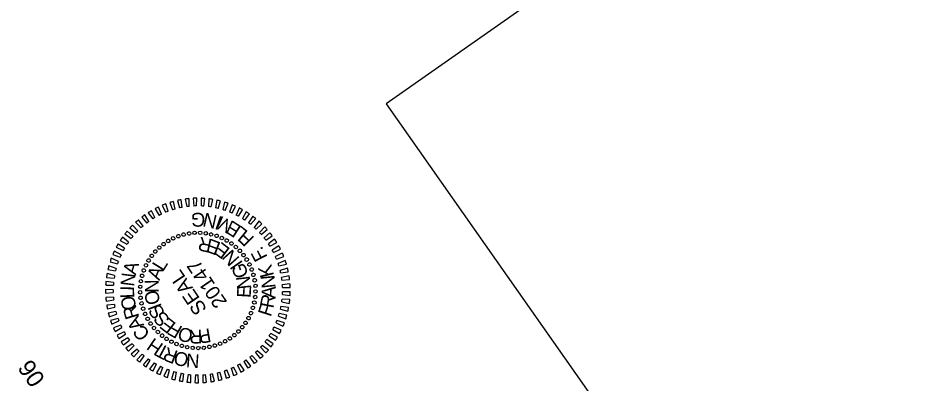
# Model space of a CAD drawing. Extents: x 2046262 to 2047823, y 758628 to 760417.
# Drawn here: x 2046261.8 to 2046652, y 759808.2 to 759966.9 of the extents above; entities that cross this region are included whole.
import ezdxf

# ---------------------------------------------------------------- set-up
doc = ezdxf.new("R2010")
doc.units = 0
for name, color, linetype in [('Sheet Clip Boundary CELL', 7, 'Continuous'), ('Sheet Data Field CELL', 7, 'Continuous'), ('Sheet PE Seal Cell', 7, 'Continuous')]:
    doc.layers.add(name, color=color, linetype=linetype)

msp = doc.modelspace()

# ---------------------------------------------------------------- linework, layer by layer
at = {"layer": 'Sheet Clip Boundary CELL'}
msp.add_lwpolyline([(2046953.28, 758800.94), (2047822.73, 759389.82), (2047107.57, 760411.26), (2046421.17, 759929.65), (2046541.36, 759758.35), (2046449.64, 759693.99), (2046540.41, 759564.59), (2046459.01, 759507.49)], close=True, dxfattribs=at)
at = {"layer": 'Sheet PE Seal Cell'}
for p, q in [((2046326.79, 759883.05), (2046325.8, 759886.25)), ((2046327.49, 759886.84), (2046328.69, 759883.7)), ((2046329.79, 759884.03), (2046329.08, 759887.31)), ((2046330.81, 759887.74), (2046331.73, 759884.52)), ((2046332.86, 759884.75), (2046332.43, 759888.08)), ((2046334.2, 759888.36), (2046334.84, 759885.07)), ((2046335.98, 759885.2), (2046335.84, 759888.55)), ((2046337.63, 759888.69), (2046337.98, 759885.35)), ((2046339.13, 759885.38), (2046339.28, 759888.74)), ((2046341.07, 759888.71), (2046341.13, 759885.36)), ((2046342.28, 759885.3), (2046342.72, 759888.62)), ((2046344.5, 759888.45), (2046344.28, 759885.1)), ((2046345.41, 759884.94), (2046346.13, 759888.21)), ((2046347.9, 759887.89), (2046347.38, 759884.57)), ((2046348.5, 759884.31), (2046349.5, 759887.51)), ((2046351.23, 759887.04), (2046350.44, 759883.78)), ((2046351.53, 759883.42), (2046352.8, 759886.53)), ((2046354.48, 759885.9), (2046353.41, 759882.72)), ((2046318.17, 759882.46), (2046320.12, 759879.73)), ((2046321.11, 759880.33), (2046319.58, 759883.32)), ((2046321.15, 759884.19), (2046322.86, 759881.3)), ((2046323.89, 759881.81), (2046322.63, 759884.92)), ((2046324.26, 759885.65), (2046325.72, 759882.63)), ((2046354.47, 759882.27), (2046356, 759885.26)), ((2046357.62, 759884.49), (2046356.28, 759881.42)), ((2046357.3, 759880.88), (2046359.08, 759883.72)), ((2046360.63, 759882.82), (2046359.03, 759879.87)), ((2046359.99, 759879.25), (2046362.01, 759881.92)), ((2046312.71, 759878.28), (2046315.1, 759875.93)), ((2046315.97, 759876.68), (2046313.95, 759879.36)), ((2046315.35, 759880.49), (2046317.53, 759877.94)), ((2046318.46, 759878.62), (2046316.68, 759881.46)), ((2046363.48, 759880.89), (2046361.63, 759878.09)), ((2046362.54, 759877.39), (2046364.78, 759879.88)), ((2046366.15, 759878.73), (2046364.07, 759876.09)), ((2046311.53, 759872.21), (2046309.09, 759874.5)), ((2046310.27, 759875.85), (2046312.86, 759873.71)), ((2046313.65, 759874.54), (2046311.41, 759877.04)), ((2046364.92, 759875.32), (2046367.37, 759877.61)), ((2046368.63, 759876.34), (2046366.33, 759873.9)), ((2046367.11, 759873.05), (2046369.75, 759875.12)), ((2046306.06, 759870.41), (2046308.98, 759868.75)), ((2046309.62, 759869.7), (2046306.98, 759871.78)), ((2046308.05, 759873.22), (2046310.81, 759871.31)), ((2046370.9, 759873.75), (2046368.4, 759871.51)), ((2046369.1, 759870.6), (2046371.9, 759872.44)), ((2046372.93, 759870.97), (2046370.25, 759868.96)), ((2046304.32, 759867.44), (2046307.37, 759866.03)), ((2046307.93, 759867.04), (2046305.13, 759868.88)), ((2046370.87, 759867.99), (2046373.82, 759869.58)), ((2046374.72, 759868.03), (2046371.87, 759866.26)), ((2046372.41, 759865.24), (2046375.49, 759866.57)), ((2046305.26, 759861.33), (2046302.19, 759862.67)), ((2046302.85, 759864.33), (2046306, 759863.19)), ((2046306.47, 759864.24), (2046303.52, 759865.84)), ((2046376.25, 759864.95), (2046373.26, 759863.42)), ((2046373.71, 759862.36), (2046376.89, 759863.43)), ((2046304.31, 759858.32), (2046301.13, 759859.39)), ((2046301.64, 759861.11), (2046304.88, 759860.24)), ((2046377.51, 759861.74), (2046374.4, 759860.48)), ((2046374.75, 759859.39), (2046378.01, 759860.17)), ((2046303.61, 759855.25), (2046300.35, 759856.04)), ((2046300.72, 759857.79), (2046304.02, 759857.21)), ((2046378.49, 759858.44), (2046375.28, 759857.45)), ((2046375.54, 759856.33), (2046378.85, 759856.83)), ((2046379.18, 759855.07), (2046375.9, 759854.36)), ((2046299.75, 759850.98), (2046303.1, 759850.98)), ((2046303.19, 759852.12), (2046299.87, 759852.63)), ((2046300.09, 759854.41), (2046303.43, 759854.11)), ((2046376.06, 759853.22), (2046379.41, 759853.44)), ((2046379.58, 759851.65), (2046376.25, 759851.23)), ((2046303.03, 759848.97), (2046299.68, 759849.19)), ((2046299.7, 759847.54), (2046303.04, 759847.82)), ((2046339.68, 759848.74), (2046339.68, 759848.74)), ((2046376.29, 759846.93), (2046379.62, 759846.56)), ((2046376.31, 759850.08), (2046379.66, 759850.01)), ((2046379.68, 759848.21), (2046376.33, 759848.08)), ((2046303.15, 759845.82), (2046299.79, 759845.75)), ((2046299.95, 759844.11), (2046303.26, 759844.68)), ((2046376, 759843.79), (2046379.29, 759843.14)), ((2046379.49, 759844.78), (2046376.13, 759844.93)), ((2046303.53, 759842.69), (2046300.2, 759842.33)), ((2046300.5, 759840.71), (2046303.74, 759841.56)), ((2046304.19, 759839.61), (2046300.89, 759838.96)), ((2046375.44, 759840.68), (2046378.66, 759839.75)), ((2046379, 759841.37), (2046375.67, 759841.81)), ((2046301.33, 759837.37), (2046304.49, 759838.5)), ((2046305.1, 759836.59), (2046301.88, 759835.67)), ((2046302.45, 759834.12), (2046305.5, 759835.51)), ((2046377.15, 759834.74), (2046373.95, 759835.75)), ((2046374.61, 759837.64), (2046377.74, 759836.44)), ((2046378.22, 759838.02), (2046374.94, 759838.74)), ((2046306.28, 759833.66), (2046303.14, 759832.46)), ((2046303.84, 759830.97), (2046306.77, 759832.62)), ((2046372.19, 759831.82), (2046375.07, 759830.1)), ((2046375.81, 759831.57), (2046372.71, 759832.85)), ((2046373.53, 759834.68), (2046376.55, 759833.21)), ((2046307.7, 759830.85), (2046304.68, 759829.38)), ((2046305.5, 759827.96), (2046308.27, 759829.85)), ((2046309.35, 759828.16), (2046306.47, 759826.45)), ((2046372.34, 759825.64), (2046369.5, 759827.43)), ((2046370.62, 759829.09), (2046373.34, 759827.13)), ((2046374.2, 759828.53), (2046371.22, 759830.07)), ((2046307.42, 759825.1), (2046310.01, 759827.22)), ((2046311.23, 759825.63), (2046308.51, 759823.67)), ((2046309.57, 759822.41), (2046311.97, 759824.75)), ((2046366.8, 759824.08), (2046369.14, 759821.68)), ((2046370.23, 759822.92), (2046367.56, 759824.94)), ((2046368.82, 759826.5), (2046371.36, 759824.31)), ((2046313.33, 759823.27), (2046310.78, 759821.09)), ((2046311.94, 759819.92), (2046314.14, 759822.46)), ((2046315.61, 759821.1), (2046313.26, 759818.7)), ((2046314.52, 759817.64), (2046316.49, 759820.36)), ((2046362.17, 759819.8), (2046364.07, 759817.03)), ((2046365.36, 759818.07), (2046363.07, 759820.52)), ((2046364.58, 759821.84), (2046366.71, 759819.25)), ((2046367.9, 759820.39), (2046365.41, 759822.63)), ((2046318.08, 759819.13), (2046315.94, 759816.54)), ((2046317.29, 759815.59), (2046319.02, 759818.47)), ((2046320.7, 759817.39), (2046318.8, 759814.62)), ((2046320.22, 759813.79), (2046321.69, 759816.81)), ((2046323.47, 759815.87), (2046321.81, 759812.95)), ((2046356.88, 759816.37), (2046358.28, 759813.32)), ((2046359.72, 759814.12), (2046357.89, 759816.93)), ((2046359.6, 759817.97), (2046361.25, 759815.05)), ((2046362.63, 759815.97), (2046360.56, 759818.61)), ((2046323.3, 759812.25), (2046324.51, 759815.38)), ((2046326.35, 759814.6), (2046324.95, 759811.55)), ((2046326.5, 759810.97), (2046327.43, 759814.2)), ((2046329.34, 759813.58), (2046328.2, 759810.42)), ((2046329.79, 759809.98), (2046330.45, 759813.27)), ((2046332.4, 759812.82), (2046331.54, 759809.58)), ((2046333.16, 759809.27), (2046333.53, 759812.61)), ((2046335.51, 759812.33), (2046334.94, 759809.02)), ((2046336.58, 759808.86), (2046336.66, 759812.21)), ((2046338.66, 759812.1), (2046338.37, 759808.76)), ((2046340.02, 759808.74), (2046339.81, 759812.09)), ((2046341.81, 759812.15), (2046341.81, 759808.8)), ((2046343.45, 759808.92), (2046342.96, 759812.24)), ((2046344.95, 759812.47), (2046345.23, 759809.13)), ((2046346.86, 759809.39), (2046346.08, 759812.65)), ((2046348.05, 759813.06), (2046348.62, 759809.75)), ((2046350.22, 759810.15), (2046349.16, 759813.34)), ((2046351.08, 759813.91), (2046351.94, 759810.66)), ((2046353.5, 759811.2), (2046352.17, 759814.28)), ((2046354.04, 759815.02), (2046355.17, 759811.86)), ((2046356.67, 759812.53), (2046355.09, 759815.48))]:
    msp.add_line(p, q, dxfattribs=at)
for radius, start, end in [(40, 110.308, 112.6716), (40, 105.3765, 107.7401), (40, 100.445, 102.8086), (40, 95.5135, 97.8771), (40, 90.5819, 92.9456), (40, 85.6504, 88.0141), (40, 80.7189, 83.0825), (40, 75.7874, 78.151), (40, 70.8559, 73.2195), (40, 65.9244, 68.288), (40, 120.171, 122.5346), (40, 115.2395, 117.6031), (36.65, 110.5908, 112.3887), (36.65, 105.6593, 107.4572), (36.65, 100.7278, 102.5257), (36.65, 95.7963, 97.5942), (36.65, 90.8648, 92.6627), (36.65, 85.9333, 87.7312), (36.65, 81.0018, 82.7997), (36.65, 76.0703, 77.8682), (36.65, 71.1388, 72.9367), (36.65, 66.2073, 68.0052), (40, 60.9929, 63.3565), (40, 56.0614, 58.425), (40, 130.034, 132.3976), (40, 125.1025, 127.4661), (36.65, 125.3854, 127.1832), (36.65, 120.4538, 122.2517), (36.65, 115.5223, 117.3202), (36.65, 61.2758, 63.0737), (36.65, 56.3443, 58.1422), (36.65, 51.4128, 53.2106), (40, 51.1299, 53.4935), (40, 46.1984, 48.562), (40, 139.897, 142.2606), (40, 134.9655, 137.3291), (36.65, 135.2484, 137.0463), (36.65, 130.3169, 132.1148), (36.65, 46.4812, 48.2791), (40, 41.2669, 43.6305), (40, 144.8285, 147.1921), (36.65, 140.1799, 141.9778), (36.65, 41.5497, 43.3476), (36.65, 36.6182, 38.4161), (40, 36.3354, 38.699), (40, 31.4039, 33.7675), (40, 149.76, 152.1236), (36.65, 150.0429, 151.8408), (36.65, 145.1114, 146.9093), (36.65, 31.6867, 33.4846), (40, 26.4724, 28.836), (40, 159.623, 161.9867), (40, 154.6915, 157.0552), (36.65, 154.9744, 156.7723), (36.65, 26.7552, 28.5531), (36.65, 21.8237, 23.6216), (40, 21.5408, 23.9045), (40, 164.5545, 166.9182), (36.65, 159.9059, 161.7038), (36.65, 16.8922, 18.6901), (40, 16.6093, 18.973), (40, 169.4861, 171.8497), (36.65, 169.7689, 171.5668), (36.65, 164.8374, 166.6353), (36.65, 11.9607, 13.7586), (40, 11.6778, 14.0415), (40, 6.7463, 9.1099), (40, 174.4176, 176.7812), (36.65, 174.7004, 176.4983), (36.65, 7.0292, 8.8271), (36.65, 2.0977, 3.8956), (40, 1.8148, 4.1784), (40, 179.3491, 181.7127), (36.65, 179.6319, 181.4298), (36.65, 357.1662, 358.9641), (40, 356.8833, 359.2469), (40, 184.2806, 186.6442), (36.65, 184.5634, 186.3613), (36.65, 352.2347, 354.0326), (40, 351.9518, 354.3154), (40, 189.2121, 191.5757), (40, 194.1436, 196.5072), (36.65, 189.4949, 191.2928), (36.65, 194.4264, 196.2243), (36.65, 347.3032, 349.1011), (40, 347.0203, 349.3839), (40, 199.0751, 201.4387), (36.65, 199.358, 201.1559), (36.65, 337.4401, 339.238), (36.65, 342.3717, 344.1695), (40, 342.0888, 344.4524), (40, 204.0066, 206.3702), (36.65, 204.2895, 206.0874), (36.65, 332.5086, 334.3065), (40, 332.2258, 334.5894), (40, 337.1573, 339.5209), (40, 208.9381, 211.3017), (36.65, 209.221, 211.0189), (36.65, 214.1525, 215.9504), (36.65, 322.6456, 324.4435), (36.65, 327.5771, 329.375), (40, 327.2943, 329.6579), (40, 213.8696, 216.2332), (40, 218.8011, 221.1647), (36.65, 219.084, 220.8819), (36.65, 317.7141, 319.512), (40, 322.3628, 324.7264), (40, 223.7326, 226.0962), (36.65, 224.0155, 225.8134), (36.65, 228.947, 230.7449), (36.65, 307.8511, 309.649), (36.65, 312.7826, 314.5805), (40, 312.4998, 314.8634), (40, 317.4313, 319.7949), (40, 228.6641, 231.0278), (40, 233.5956, 235.9593), (36.65, 233.8785, 235.6764), (36.65, 238.81, 240.6079), (36.65, 243.7415, 245.5394), (36.65, 297.9881, 299.786), (36.65, 302.9196, 304.7175), (40, 302.6367, 305.0004), (40, 307.5682, 309.9319), (40, 238.5271, 240.8908), (40, 243.4587, 245.8223), (36.65, 248.673, 250.4709), (36.65, 253.6045, 255.4024), (36.65, 258.536, 260.3339), (36.65, 263.4675, 265.2654), (36.65, 268.3991, 270.1969), (36.65, 273.3306, 275.1285), (36.65, 278.2621, 280.06), (36.65, 283.1936, 284.9915), (36.65, 288.1251, 289.923), (36.65, 293.0566, 294.8545), (40, 292.7737, 295.1373), (40, 297.7052, 300.0688), (40, 248.3902, 250.7538), (40, 253.3217, 255.6853), (40, 258.2532, 260.6168), (40, 263.1847, 265.5483), (40, 268.1162, 270.4798), (40, 273.0477, 275.4113), (40, 277.9792, 280.3428), (40, 282.9107, 285.2743), (40, 287.8422, 290.2058)]:
    msp.add_arc((2046339.68, 759848.74), radius, start, end, dxfattribs=at)
for centre, major_axis in [((2046335.88, 759873.45), (-0.164, 0.724)), ((2046338.28, 759873.7), (-0.093, 0.736)), ((2046340.7, 759873.72), (-0.022, 0.742)), ((2046343.11, 759873.5), (0.05, 0.741)), ((2046326.84, 759870.19), (-0.425, 0.609)), ((2046328.97, 759871.33), (-0.364, 0.647)), ((2046331.21, 759872.26), (-0.3, 0.679)), ((2046333.51, 759872.97), (-0.233, 0.705)), ((2046345.48, 759873.06), (0.121, 0.732)), ((2046347.8, 759872.38), (0.191, 0.717)), ((2046350.04, 759871.49), (0.26, 0.695)), ((2046352.19, 759870.38), (0.326, 0.667)), ((2046321.25, 759865.62), (-0.581, 0.462)), ((2046322.96, 759867.32), (-0.534, 0.516)), ((2046324.83, 759868.85), (-0.481, 0.565)), ((2046354.22, 759869.08), (0.389, 0.633)), ((2046356.12, 759867.58), (0.448, 0.592)), ((2046357.86, 759865.9), (0.503, 0.546)), ((2046318.35, 759861.77), (-0.659, 0.342)), ((2046319.7, 759863.77), (-0.623, 0.404)), ((2046359.43, 759864.07), (0.553, 0.495)), ((2046360.82, 759862.09), (0.598, 0.439)), ((2046317.19, 759859.65), (-0.689, 0.277)), ((2046362.01, 759859.99), (0.638, 0.379)), ((2046362.99, 759857.78), (0.672, 0.316)), ((2046315.51, 759855.12), (-0.729, 0.139)), ((2046316.24, 759857.43), (-0.712, 0.209)), ((2046363.75, 759855.49), (0.699, 0.25)), ((2046314.73, 759850.36), (-0.742, -0.004)), ((2046315.01, 759852.76), (-0.739, 0.068)), ((2046364.29, 759853.13), (0.72, 0.181)), ((2046364.6, 759850.74), (0.734, 0.111)), ((2046314.69, 759847.94), (-0.739, -0.075)), ((2046364.68, 759848.32), (0.741, 0.04)), ((2046314.89, 759845.54), (-0.728, -0.146)), ((2046315.31, 759843.16), (-0.71, -0.216)), ((2046364.13, 759843.53), (0.735, -0.104)), ((2046364.52, 759845.91), (0.742, -0.032)), ((2046315.97, 759840.83), (-0.686, -0.283)), ((2046316.84, 759838.58), (-0.656, -0.348)), ((2046362.68, 759838.93), (0.701, -0.243)), ((2046363.52, 759841.19), (0.722, -0.174)), ((2046317.93, 759836.42), (-0.619, -0.41)), ((2046319.22, 759834.38), (-0.576, -0.468)), ((2046360.36, 759834.69), (0.642, -0.373)), ((2046361.62, 759836.76), (0.675, -0.31)), ((2046320.7, 759832.47), (-0.529, -0.521)), ((2046322.36, 759830.72), (-0.476, -0.57)), ((2046357.28, 759830.98), (0.558, -0.49)), ((2046358.91, 759832.76), (0.603, -0.433)), ((2046324.18, 759829.13), (-0.419, -0.613)), ((2046326.14, 759827.72), (-0.358, -0.651)), ((2046328.23, 759826.51), (-0.293, -0.682)), ((2046351.47, 759826.69), (0.395, -0.629)), ((2046353.54, 759827.93), (0.454, -0.588)), ((2046355.48, 759829.37), (0.508, -0.541)), ((2046330.43, 759825.51), (-0.226, -0.707)), ((2046332.72, 759824.73), (-0.157, -0.726)), ((2046335.07, 759824.17), (-0.086, -0.737)), ((2046337.46, 759823.84), (-0.014, -0.742)), ((2046339.87, 759823.74), (0.057, -0.74)), ((2046342.28, 759823.87), (0.129, -0.731)), ((2046344.67, 759824.24), (0.199, -0.715)), ((2046347.01, 759824.84), (0.267, -0.693)), ((2046349.29, 759825.66), (0.332, -0.664))]:
    msp.add_ellipse(centre, major_axis=major_axis, ratio=0.999708, dxfattribs=at)

# ---------------------------------------------------------------- texts
at = {"layer": 'Sheet Data Field CELL'}
msp.add_text('06', height=7.5, rotation=125.0179, dxfattribs=at).set_placement((2046273.82, 759810.32))
at = {"layer": 'Sheet PE Seal Cell'}
for s, height, rotation, p in [('G', 6, 176.4994, (2046343.05, 759882.2)), ('N', 6, 167.1631, (2046348.41, 759881.22)), ('I', 6, 160.8076, (2046350.67, 759880.5)), ('M', 6, 155.8614, (2046355.53, 759878.48)), ('E', 6, 147.2191, (2046358.96, 759876.31)), ('L', 6, 141.1027, (2046361.74, 759874.14)), ('R', 6, 168.0491, (2046346.16, 759870.87)), ('E', 6, 159.2961, (2046349.99, 759869.4)), ('F', 6, 135.063, (2046364.48, 759871.49)), ('E', 6, 142.8924, (2046354.02, 759866.72)), ('N', 6, 132.0432, (2046358.07, 759862.69)), ('.', 6, 115.6098, (2046368.22, 759866.35)), ('F', 6, 117.2455, (2046370.03, 759863.24)), ('A', 6, 73.7281, (2046312.78, 759855.15)), ('L', 6, 58.1401, (2046324.6, 759856.68)), ('20147', 6.185, 124.0514, (2046352.55, 759843.77)), ('I', 6, 124.5937, (2046359.43, 759860.57)), ('G', 6, 109.009, (2046361.73, 759855.28)), ('K', 6, 104.0824, (2046372.72, 759855.21)), ('N', 6, 82.6584, (2046312.03, 759850.23)), ('A', 6, 68.2732, (2046323, 759852.76)), ('SEAL', 6.184, 124.0514, (2046343.85, 759840.71)), ('N', 6, 96.4793, (2046362.73, 759849.6)), ('N', 6, 95.708, (2046373.35, 759849.95)), ('N', 6, 90.7935, (2046322.73, 759847.77)), ('I', 6, 88.4949, (2046312.05, 759848.49)), ('L', 6, 92.4825, (2046312.19, 759845.43)), ('O', 6, 102.507, (2046323.49, 759843.23)), ('E', 6, 86.6258, (2046362.51, 759845.38)), ('R', 6, 79.0203, (2046372.38, 759840.77)), ('A', 6, 86.4683, (2046373.14, 759845.14)), ('O', 6, 99.6828, (2046313.07, 759840.66)), ('I', 6, 110.8969, (2046324.18, 759841.69)), ('F', 6, 71.8129, (2046371.22, 759837.03)), ('R', 6, 106.9721, (2046314.35, 759837.34)), ('S', 6, 125.0568, (2046325.78, 759839.04)), ('S', 6, 133.437, (2046327.95, 759836.41)), ('A', 6, 122.4593, (2046316.55, 759833.72)), ('E', 6, 142.2361, (2046330.59, 759834.28)), ('C', 6, 131.3437, (2046319.32, 759830.1)), ('F', 6, 150.4633, (2046333.43, 759832.78)), ('O', 6, 169.411, (2046337.88, 759831.8)), ('R', 6, 181.3373, (2046341.58, 759831.78)), ('P', 6, 189.8445, (2046344.81, 759832.4)), ('H', 6, 145.7126, (2046325.16, 759825.22)), ('T', 6, 152.1057, (2046327.89, 759823.73)), ('R', 6, 159.2027, (2046331.5, 759822.3)), ('O', 6, 166.8653, (2046336.2, 759821.2)), ('N', 6, 175.885, (2046340.59, 759821))]:
    msp.add_text(s, height=height, rotation=rotation, dxfattribs=at).set_placement(p)

doc.saveas('drawing.dxf')
